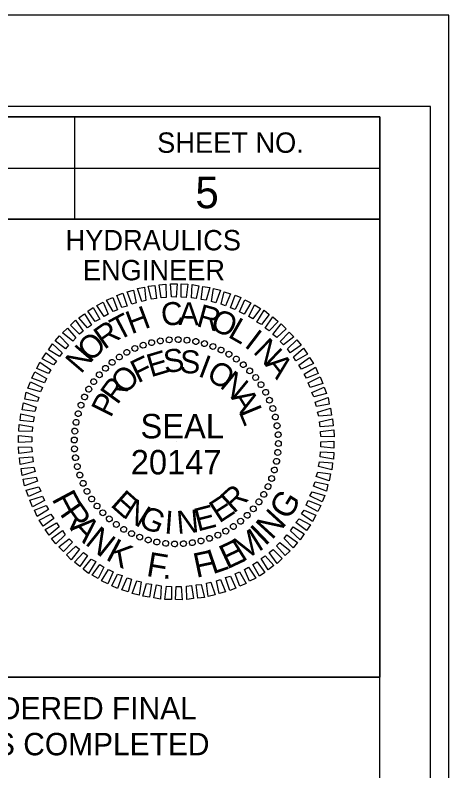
# Model space of a CAD drawing. Extents: x 572694 to 574378, y -52955 to -51855.
# Drawn here: x 574271.9 to 574378.5, y -52040.7 to -51855.1 of the extents above; entities that cross this region are included whole.
import ezdxf

# ---------------------------------------------------------------- set-up
doc = ezdxf.new("R2010")
doc.units = 0
for name, color, linetype in [('Sheet Cutting Line CELL', 7, 'Continuous'), ('Sheet Data Field CELL', 7, 'Continuous'), ('Sheet PE Seal Cell', 7, 'Continuous'), ('Sheet Plot Border Inside CELL', 7, 'Continuous'), ('Sheet Plot Border Outside CELL', 7, 'Continuous'), ('Sheet Profile CELL', 7, 'Continuous'), ('Sheet Sticker Exception Certification CELL', 7, 'Continuous')]:
    doc.layers.add(name, color=color, linetype=linetype)

msp = doc.modelspace()

# ---------------------------------------------------------------- linework, layer by layer
at = {"layer": 'Sheet Cutting Line CELL'}
msp.add_line((574378.5, -51855.14), (572694.5, -51855.14), dxfattribs=at)
at = {"layer": 'Sheet PE Seal Cell'}
for p, q in [((574305.41, -51935.53), (574305.41, -51935.53)), ((574307.61, -51935.13), (574307.61, -51935.13)), ((574309.76, -51934.83), (574309.76, -51934.83)), ((574311.96, -51934.78), (574311.96, -51934.78)), ((574314.16, -51934.93), (574314.16, -51934.93)), ((574316.31, -51935.28), (574316.31, -51935.28)), ((574318.41, -51935.73), (574318.41, -51935.73)), ((574301.31, -51936.93), (574301.31, -51936.93)), ((574303.31, -51936.13), (574303.31, -51936.13)), ((574320.51, -51936.43), (574320.51, -51936.43)), ((574322.51, -51937.33), (574322.51, -51937.33)), ((574297.46, -51939.08), (574297.46, -51939.08)), ((574299.36, -51937.93), (574299.36, -51937.93)), ((574324.46, -51938.33), (574324.46, -51938.33)), ((574295.71, -51940.33), (574295.71, -51940.33)), ((574326.26, -51939.58), (574326.26, -51939.58)), ((574328.01, -51940.93), (574328.01, -51940.93)), ((574294.06, -51941.83), (574294.06, -51941.83)), ((574329.56, -51942.43), (574329.56, -51942.43)), ((574291.21, -51945.13), (574291.21, -51945.13)), ((574292.56, -51943.38), (574292.56, -51943.38)), ((574331.06, -51944.08), (574331.06, -51944.08)), ((574289.96, -51946.93), (574289.96, -51946.93)), ((574332.31, -51945.83), (574332.31, -51945.83)), ((574333.46, -51947.73), (574333.46, -51947.73)), ((574288.96, -51948.88), (574288.96, -51948.88)), ((574334.46, -51949.68), (574334.46, -51949.68)), ((574288.06, -51950.88), (574288.06, -51950.88)), ((574335.26, -51951.68), (574335.26, -51951.68)), ((574287.36, -51952.98), (574287.36, -51952.98)), ((574335.86, -51953.78), (574335.86, -51953.78)), ((574286.91, -51955.08), (574286.91, -51955.08)), ((574336.26, -51955.98), (574336.26, -51955.98)), ((574286.56, -51957.23), (574286.56, -51957.23)), ((574336.56, -51958.13), (574336.56, -51958.13)), ((574286.41, -51959.43), (574286.41, -51959.43)), ((574311.51, -51959.88), (574311.51, -51959.88)), ((574286.46, -51961.63), (574286.46, -51961.63)), ((574336.61, -51960.33), (574336.61, -51960.33)), ((574336.46, -51962.53), (574336.46, -51962.53)), ((574286.76, -51963.78), (574286.76, -51963.78)), ((574336.11, -51964.68), (574336.11, -51964.68)), ((574287.16, -51965.98), (574287.16, -51965.98)), ((574335.66, -51966.78), (574335.66, -51966.78)), ((574287.76, -51968.08), (574287.76, -51968.08)), ((574334.96, -51968.88), (574334.96, -51968.88)), ((574288.56, -51970.08), (574288.56, -51970.08)), ((574334.06, -51970.88), (574334.06, -51970.88)), ((574289.56, -51972.03), (574289.56, -51972.03)), ((574333.06, -51972.83), (574333.06, -51972.83)), ((574290.71, -51973.93), (574290.71, -51973.93)), ((574331.81, -51974.63), (574331.81, -51974.63)), ((574291.96, -51975.68), (574291.96, -51975.68)), ((574330.46, -51976.38), (574330.46, -51976.38)), ((574293.46, -51977.33), (574293.46, -51977.33)), ((574328.96, -51977.93), (574328.96, -51977.93)), ((574295.01, -51978.83), (574295.01, -51978.83)), ((574296.76, -51980.18), (574296.76, -51980.18)), ((574327.31, -51979.43), (574327.31, -51979.43)), ((574298.56, -51981.43), (574298.56, -51981.43)), ((574323.66, -51981.83), (574323.66, -51981.83)), ((574325.56, -51980.68), (574325.56, -51980.68)), ((574300.51, -51982.43), (574300.51, -51982.43)), ((574302.51, -51983.33), (574302.51, -51983.33)), ((574304.61, -51984.03), (574304.61, -51984.03)), ((574319.71, -51983.63), (574319.71, -51983.63)), ((574321.71, -51982.83), (574321.71, -51982.83)), ((574306.71, -51984.48), (574306.71, -51984.48)), ((574308.86, -51984.83), (574308.86, -51984.83)), ((574311.06, -51984.98), (574311.06, -51984.98)), ((574313.26, -51984.93), (574313.26, -51984.93)), ((574315.41, -51984.63), (574315.41, -51984.63)), ((574317.61, -51984.23), (574317.61, -51984.23))]:
    msp.add_line(p, q, dxfattribs=at)
for points in [[(574300.61, -51926.08), (574299.46, -51923.08), (574301.01, -51922.63), (574301.66, -51925.73)], [(574303.01, -51925.43), (574301.96, -51922.28), (574303.66, -51921.93), (574304.06, -51925.18)], [(574305.41, -51924.88), (574304.61, -51921.68), (574306.26, -51921.53), (574306.61, -51924.73)], [(574307.81, -51924.58), (574307.26, -51921.38), (574308.96, -51921.18), (574309.01, -51924.43)], [(574310.31, -51924.33), (574310.06, -51921.08), (574311.71, -51921.13), (574311.51, -51924.38)], [(574312.71, -51924.38), (574312.71, -51921.13), (574314.36, -51921.18), (574313.91, -51924.43)], [(574315.21, -51924.53), (574315.41, -51921.28), (574317.06, -51921.58), (574316.41, -51924.73)], [(574317.61, -51924.93), (574318.06, -51921.73), (574319.71, -51921.98), (574318.81, -51925.08)], [(574320.16, -51925.48), (574320.66, -51922.23), (574322.36, -51922.63), (574321.21, -51925.73)], [(574295.96, -51927.93), (574294.36, -51925.13), (574295.91, -51924.43), (574297.06, -51927.48)], [(574298.16, -51926.88), (574296.86, -51923.98), (574298.36, -51923.38), (574299.41, -51926.58)], [(574322.56, -51926.13), (574323.31, -51923.03), (574324.86, -51923.53), (574323.61, -51926.48)], [(574324.81, -51927.03), (574325.96, -51923.88), (574327.36, -51924.48), (574325.96, -51927.38)], [(574293.81, -51929.13), (574291.96, -51926.43), (574293.51, -51925.63), (574294.76, -51928.53)], [(574327.06, -51927.98), (574328.31, -51925.03), (574329.86, -51925.73), (574328.16, -51928.53)], [(574329.36, -51929.13), (574330.71, -51926.28), (574332.21, -51927.13), (574330.31, -51929.73)], [(574289.71, -51931.88), (574287.56, -51929.48), (574288.91, -51928.43), (574290.66, -51931.23)], [(574291.61, -51930.38), (574289.76, -51927.83), (574291.06, -51926.88), (574292.71, -51929.78)], [(574331.31, -51930.48), (574333.06, -51927.58), (574334.36, -51928.63), (574332.41, -51931.08)], [(574287.71, -51933.43), (574285.51, -51931.23), (574286.71, -51930.03), (574288.66, -51932.73)], [(574333.36, -51931.98), (574335.21, -51929.23), (574336.51, -51930.33), (574334.31, -51932.68)], [(574286.06, -51935.18), (574283.51, -51933.13), (574284.76, -51931.98), (574286.86, -51934.38)], [(574335.26, -51933.53), (574337.31, -51930.93), (574338.51, -51932.13), (574336.21, -51934.28)], [(574284.31, -51937.08), (574281.71, -51935.13), (574282.81, -51933.83), (574285.01, -51936.18)], [(574337.06, -51935.28), (574339.21, -51932.93), (574340.41, -51934.13), (574337.81, -51936.08)], [(574282.81, -51938.98), (574280.11, -51937.28), (574281.06, -51935.83), (574283.46, -51938.03)], [(574338.81, -51937.08), (574341.11, -51934.83), (574342.16, -51936.18), (574339.51, -51938.08)], [(574340.31, -51939.03), (574342.76, -51936.93), (574343.71, -51938.38), (574340.91, -51939.98)], [(574281.31, -51940.98), (574278.51, -51939.48), (574279.51, -51938.08), (574282.11, -51940.08)], [(574341.61, -51941.08), (574344.26, -51939.18), (574345.21, -51940.68), (574342.31, -51942.08)], [(574280.11, -51943.13), (574277.26, -51941.88), (574278.01, -51940.33), (574280.71, -51942.18)], [(574279.11, -51945.43), (574276.01, -51944.28), (574276.76, -51942.73), (574279.61, -51944.33)], [(574342.91, -51943.28), (574345.71, -51941.53), (574346.36, -51943.08), (574343.51, -51944.23)], [(574343.91, -51945.43), (574346.86, -51943.93), (574347.51, -51945.53), (574344.41, -51946.53)], [(574278.11, -51947.63), (574275.01, -51946.73), (574275.66, -51945.18), (574278.66, -51946.58)], [(574344.81, -51947.78), (574347.86, -51946.48), (574348.41, -51948.03), (574345.31, -51948.83)], [(574277.36, -51950.03), (574274.26, -51949.38), (574274.61, -51947.73), (574277.76, -51948.98)], [(574276.71, -51952.43), (574273.61, -51952.03), (574273.96, -51950.33), (574277.11, -51951.38)], [(574345.61, -51950.18), (574348.81, -51949.03), (574349.11, -51950.68), (574345.96, -51951.23)], [(574346.21, -51952.58), (574349.36, -51951.63), (574349.66, -51953.33), (574346.51, -51953.63)], [(574276.31, -51954.98), (574273.11, -51954.68), (574273.31, -51952.98), (574276.56, -51953.78)], [(574346.66, -51954.98), (574349.91, -51954.28), (574350.06, -51955.98), (574346.86, -51956.18)], [(574276.06, -51957.38), (574272.81, -51957.28), (574272.91, -51955.63), (574276.16, -51956.18)], [(574346.96, -51957.38), (574350.21, -51956.98), (574350.31, -51958.68), (574347.06, -51958.58)], [(574276.01, -51959.88), (574272.76, -51960.03), (574272.76, -51958.33), (574276.01, -51958.68)], [(574347.01, -51959.88), (574350.26, -51959.73), (574350.26, -51961.43), (574347.01, -51961.08)], [(574276.06, -51962.38), (574272.81, -51962.78), (574272.71, -51961.08), (574275.96, -51961.18)], [(574276.36, -51964.78), (574273.11, -51965.48), (574272.96, -51963.78), (574276.16, -51963.58)], [(574346.96, -51962.38), (574350.21, -51962.48), (574350.11, -51964.13), (574346.86, -51963.58)], [(574346.71, -51964.78), (574349.91, -51965.08), (574349.71, -51966.78), (574346.46, -51965.98)], [(574276.81, -51967.18), (574273.66, -51968.13), (574273.36, -51966.43), (574276.51, -51966.13)], [(574346.31, -51967.33), (574349.41, -51967.73), (574349.06, -51969.43), (574345.91, -51968.38)], [(574277.41, -51969.58), (574274.21, -51970.73), (574273.91, -51969.08), (574277.06, -51968.53)], [(574278.21, -51971.98), (574275.16, -51973.28), (574274.61, -51971.73), (574277.71, -51970.93)], [(574345.66, -51969.73), (574348.76, -51970.38), (574348.41, -51972.03), (574345.26, -51970.78)], [(574344.91, -51972.13), (574348.01, -51973.03), (574347.36, -51974.58), (574344.36, -51973.18)], [(574279.11, -51974.33), (574276.16, -51975.83), (574275.51, -51974.23), (574278.61, -51973.23)], [(574343.91, -51974.33), (574347.01, -51975.48), (574346.26, -51977.03), (574343.41, -51975.43)], [(574280.11, -51976.48), (574277.31, -51978.23), (574276.66, -51976.68), (574279.51, -51975.53)], [(574342.91, -51976.63), (574345.76, -51977.88), (574345.01, -51979.43), (574342.31, -51977.58)], [(574281.41, -51978.68), (574278.76, -51980.58), (574277.81, -51979.08), (574280.71, -51977.68)], [(574282.71, -51980.73), (574280.26, -51982.83), (574279.31, -51981.38), (574282.11, -51979.78)], [(574341.71, -51978.78), (574344.51, -51980.28), (574343.51, -51981.68), (574340.91, -51979.68)], [(574284.21, -51982.68), (574281.91, -51984.93), (574280.86, -51983.58), (574283.51, -51981.68)], [(574340.21, -51980.78), (574342.91, -51982.48), (574341.96, -51983.93), (574339.56, -51981.73)], [(574285.96, -51984.48), (574283.81, -51986.83), (574282.61, -51985.63), (574285.21, -51983.68)], [(574338.71, -51982.68), (574341.31, -51984.63), (574340.21, -51985.93), (574338.01, -51983.58)], [(574287.76, -51986.23), (574285.71, -51988.83), (574284.51, -51987.63), (574286.81, -51985.48)], [(574336.96, -51984.58), (574339.51, -51986.63), (574338.26, -51987.78), (574336.16, -51985.38)], [(574289.66, -51987.78), (574287.81, -51990.53), (574286.51, -51989.43), (574288.71, -51987.08)], [(574335.31, -51986.33), (574337.51, -51988.53), (574336.31, -51989.73), (574334.36, -51987.03)], [(574291.71, -51989.28), (574289.96, -51992.18), (574288.66, -51991.13), (574290.61, -51988.68)], [(574331.41, -51989.38), (574333.26, -51991.93), (574331.96, -51992.88), (574330.31, -51989.98)], [(574333.31, -51987.88), (574335.46, -51990.28), (574334.11, -51991.33), (574332.36, -51988.53)], [(574293.66, -51990.63), (574292.31, -51993.48), (574290.81, -51992.63), (574292.71, -51990.03)], [(574295.96, -51991.78), (574294.71, -51994.73), (574293.16, -51994.03), (574294.86, -51991.23)], [(574329.21, -51990.63), (574331.06, -51993.33), (574329.51, -51994.13), (574328.26, -51991.23)], [(574298.21, -51992.73), (574297.06, -51995.88), (574295.66, -51995.28), (574297.06, -51992.38)], [(574300.46, -51993.63), (574299.71, -51996.73), (574298.16, -51996.23), (574299.41, -51993.28)], [(574324.86, -51992.88), (574326.16, -51995.78), (574324.66, -51996.38), (574323.61, -51993.18)], [(574327.06, -51991.83), (574328.66, -51994.63), (574327.11, -51995.33), (574325.96, -51992.28)], [(574302.86, -51994.28), (574302.36, -51997.53), (574300.66, -51997.13), (574301.81, -51994.03)], [(574305.41, -51994.83), (574304.96, -51998.03), (574303.31, -51997.78), (574304.21, -51994.68)], [(574307.81, -51995.23), (574307.61, -51998.48), (574305.96, -51998.18), (574306.61, -51995.03)], [(574315.21, -51995.18), (574315.76, -51998.38), (574314.06, -51998.58), (574314.01, -51995.33)], [(574317.61, -51994.88), (574318.41, -51998.08), (574316.76, -51998.23), (574316.41, -51995.03)], [(574320.01, -51994.33), (574321.06, -51997.48), (574319.36, -51997.83), (574318.96, -51994.58)], [(574322.41, -51993.68), (574323.56, -51996.68), (574322.01, -51997.13), (574321.36, -51994.03)], [(574310.31, -51995.38), (574310.31, -51998.63), (574308.66, -51998.58), (574309.11, -51995.33)], [(574312.71, -51995.43), (574312.96, -51998.68), (574311.31, -51998.63), (574311.51, -51995.38)]]:
    msp.add_lwpolyline(points, close=True, dxfattribs=at)
for centre, major_axis in [((574303.35, -51936.17), (-0.234, 0.681)), ((574305.44, -51935.54), (-0.174, 0.699)), ((574307.59, -51935.11), (-0.113, 0.711)), ((574309.76, -51934.86), (-0.05, 0.718)), ((574311.95, -51934.8), (0.013, 0.72)), ((574314.13, -51934.94), (0.075, 0.716)), ((574316.3, -51935.26), (0.137, 0.707)), ((574318.42, -51935.77), (0.198, 0.692)), ((574320.5, -51936.47), (0.258, 0.672)), ((574299.35, -51937.94), (-0.349, 0.63)), ((574301.31, -51936.97), (-0.293, 0.658)), ((574322.51, -51937.34), (0.316, 0.647)), ((574324.43, -51938.38), (0.371, 0.617)), ((574295.73, -51940.39), (-0.453, 0.56)), ((574297.49, -51939.09), (-0.403, 0.597)), ((574326.25, -51939.59), (0.423, 0.582)), ((574294.09, -51941.84), (-0.5, 0.518)), ((574327.97, -51940.95), (0.472, 0.543)), ((574292.58, -51943.43), (-0.543, 0.472)), ((574329.55, -51942.46), (0.518, 0.5)), ((574331, -51944.1), (0.56, 0.453)), ((574291.22, -51945.14), (-0.582, 0.423)), ((574332.3, -51945.85), (0.597, 0.403)), ((574290.01, -51946.96), (-0.617, 0.371)), ((574333.45, -51947.72), (0.63, 0.349)), ((574288.97, -51948.89), (-0.647, 0.316)), ((574288.1, -51950.89), (-0.672, 0.258)), ((574334.42, -51949.68), (0.658, 0.293)), ((574287.4, -51952.97), (-0.692, 0.198)), ((574335.23, -51951.71), (0.681, 0.234)), ((574286.89, -51955.09), (-0.707, 0.137)), ((574335.85, -51953.81), (0.699, 0.174)), ((574336.28, -51955.96), (0.711, 0.113)), ((574286.57, -51957.26), (-0.716, 0.075)), ((574336.53, -51958.13), (0.718, 0.05)), ((574286.44, -51959.44), (-0.72, 0.013)), ((574336.59, -51960.32), (0.72, -0.013)), ((574286.49, -51961.63), (-0.718, -0.05)), ((574336.45, -51962.5), (0.716, -0.075)), ((574286.74, -51963.8), (-0.711, -0.113)), ((574287.18, -51965.95), (-0.699, -0.174)), ((574336.13, -51964.66), (0.707, -0.137)), ((574287.8, -51968.04), (-0.681, -0.234)), ((574335.62, -51966.79), (0.692, -0.198)), ((574288.6, -51970.08), (-0.658, -0.293)), ((574334.93, -51968.87), (0.672, -0.258)), ((574334.05, -51970.87), (0.647, -0.316)), ((574289.58, -51972.04), (-0.63, -0.349)), ((574333.01, -51972.8), (0.617, -0.371)), ((574290.72, -51973.9), (-0.597, -0.403)), ((574331.8, -51974.62), (0.582, -0.423)), ((574292.02, -51975.66), (-0.56, -0.453)), ((574293.47, -51977.3), (-0.518, -0.5)), ((574330.44, -51976.33), (0.543, -0.472)), ((574295.06, -51978.81), (-0.472, -0.543)), ((574328.93, -51977.92), (0.5, -0.518)), ((574296.77, -51980.17), (-0.423, -0.582)), ((574325.54, -51980.67), (0.403, -0.597)), ((574327.3, -51979.37), (0.453, -0.56)), ((574298.59, -51981.38), (-0.371, -0.617)), ((574300.52, -51982.42), (-0.316, -0.647)), ((574321.71, -51982.79), (0.293, -0.658)), ((574323.67, -51981.81), (0.349, -0.63)), ((574302.52, -51983.29), (-0.258, -0.672)), ((574304.6, -51983.99), (-0.198, -0.692)), ((574306.73, -51984.5), (-0.137, -0.707)), ((574308.89, -51984.82), (-0.075, -0.716)), ((574315.44, -51984.65), (0.113, -0.711)), ((574317.58, -51984.21), (0.174, -0.699)), ((574319.68, -51983.59), (0.234, -0.681)), ((574311.07, -51984.96), (-0.013, -0.72)), ((574313.26, -51984.9), (0.05, -0.718))]:
    msp.add_ellipse(centre, major_axis=major_axis, ratio=0.999708, dxfattribs=at)
at = {"layer": 'Sheet Plot Border Inside CELL'}
msp.add_lwpolyline([(574374, -51877.59), (572707.5, -51877.59), (572707.5, -52932.69), (574374, -52932.69)], close=True, dxfattribs=at)
at = {"layer": 'Sheet Plot Border Outside CELL'}
msp.add_lwpolyline([(574378.5, -51855.14), (572694.5, -51855.14), (572694.5, -52955.14), (574378.5, -52955.14)], close=True, dxfattribs=at)
at = {"layer": 'Sheet Profile CELL'}
for p, q in [((574286.5, -51880.19), (574286.5, -51905.19)), ((574161.45, -51892.69), (574361.5, -51892.69))]:
    msp.add_line(p, q, dxfattribs=at)
for points in [[(574361.5, -51880.14), (572861.5, -51880.14), (572861.5, -52930.14), (574361.5, -52930.14)], [(574161.45, -51880.14), (574361.5, -51880.14), (574361.5, -51905.19), (574161.45, -51905.19)], [(574261.5, -51905.19), (574361.5, -51905.19), (574361.5, -52017.69), (574261.5, -52017.69)]]:
    msp.add_lwpolyline(points, close=True, dxfattribs=at)
at = {"layer": 'Sheet Sticker Exception Certification CELL'}
for p, q in [((574161.45, -52017.69), (574361.48, -52017.69)), ((574361.48, -52017.7), (574361.48, -52041.2))]:
    msp.add_line(p, q, dxfattribs=at)

# ---------------------------------------------------------------- texts
at = {"layer": 'Sheet Data Field CELL'}
msp.add_text(' 5 ', height=7.75, dxfattribs=at).set_placement((574313.31, -51902.54))
at = {"layer": 'Sheet PE Seal Cell'}
for s, height, rotation, p in [('H', 5.64, 20.6195, (574300.46, -51933.53)), ('C', 5.64, 6.2199, (574308.06, -51931.53)), ('A', 5.64, 359.0203, (574312.01, -51931.23)), ('R', 5.64, 344.6211, (574316.21, -51931.43)), ('T', 5.64, 27.8198, (574297.21, -51935.18)), ('O', 5.64, 337.4212, (574319.56, -51932.18)), ('L', 5.64, 330.2209, (574323.96, -51934.03)), ('R', 5.64, 35.0205, (574293.81, -51937.38)), ('O', 5.64, 42.2217, (574290.36, -51940.48)), ('I', 5.64, 323.0201, (574328.01, -51936.43)), ('N', 5.64, 315.8189, (574330.16, -51937.98)), ('N', 5.64, 49.4235, (574288.06, -51943.38)), ('E', 5.64, 16.6111, (574305.26, -51944.08)), ('S', 5.64, 7.2556, (574308.71, -51943.03)), ('S', 5.64, 357.9004, (574312.31, -51942.98)), ('F', 5.64, 25.967, (574302.06, -51945.58)), ('I', 5.64, 339.1896, (574316.61, -51943.68)), ('A', 5.64, 308.6172, (574333.11, -51940.93)), ('O', 5.64, 329.8335, (574318.61, -51944.38)), ('O', 5.64, 44.6812, (574298.76, -51948.53)), ('N', 5.64, 320.4766, (574321.96, -51946.38)), ('R', 5.64, 54.0397, (574297.01, -51950.98)), ('P', 5.64, 63.3989, (574295.41, -51954.18)), ('A', 5.64, 301.7603, (574324.81, -51948.98)), ('L', 5.64, 292.4008, (574326.76, -51952.43)), ('SEAL', 5.998, 360, (574302.71, -51959.03)), ('R', 5.64, 42.4814, (574325.61, -51977.63)), ('F', 6, 298.0174, (574280.79, -51973.89)), ('E', 5.64, 318.2769, (574295.11, -51975.53)), ('E', 5.64, 33.1241, (574322.06, -51979.98)), ('G', 6, 58.2734, (574339.09, -51979.36)), ('R', 6, 305.034, (574282.73, -51977.54)), ('N', 5.64, 327.634, (574298.11, -51978.23)), ('G', 5.64, 336.9902, (574301.91, -51980.48)), ('N', 5.64, 5.0564, (574311.81, -51982.53)), ('E', 5.64, 14.4118, (574316.76, -51981.93)), ('N', 6, 47.5476, (574334.98, -51984.15)), ('I', 5.64, 355.7012, (574308.46, -51982.38)), ('A', 6, 312.5143, (574285.28, -51981.13)), ('I', 6, 43.7456, (574333.32, -51985.65)), ('N', 6, 321.3546, (574288.85, -51984.91)), ('M', 6, 32.2161, (574327.73, -51989.49)), ('K', 6, 332.0804, (574293.91, -51988.69)), ('E', 6, 25.1068, (574323.94, -51991.27)), ('F', 6, 350.5647, (574303.95, -51992.79)), ('F', 6, 11.8154, (574316.39, -51993.29)), ('L', 6, 18.832, (574320.44, -51992.44)), ('.', 6, 357.5813, (574308.03, -51993.46))]:
    msp.add_text(s, height=height, rotation=rotation, dxfattribs=at).set_placement(p)
msp.add_text('20147', height=5.998, dxfattribs=at).set_placement((574300.31, -51967.89))
at = {"layer": 'Sheet Profile CELL'}
for s, p in [('SHEET NO.', (574306.8, -51888.94)), ('HYDRAULICS', (574284.3, -51912.89)), ('ENGINEER', (574288.55, -51920.24))]:
    msp.add_text(s, height=5, dxfattribs=at).set_placement(p)
at = {"layer": 'Sheet Sticker Exception Certification CELL'}
for s, p in [('DOCUMENT NOT CONSIDERED FINAL', (574182.52, -52028.04)), ('UNLESS ALL SIGNATURES COMPLETED', (574177.44, -52036.84))]:
    msp.add_text(s, height=5.5, dxfattribs=at).set_placement(p)

doc.saveas('drawing.dxf')
